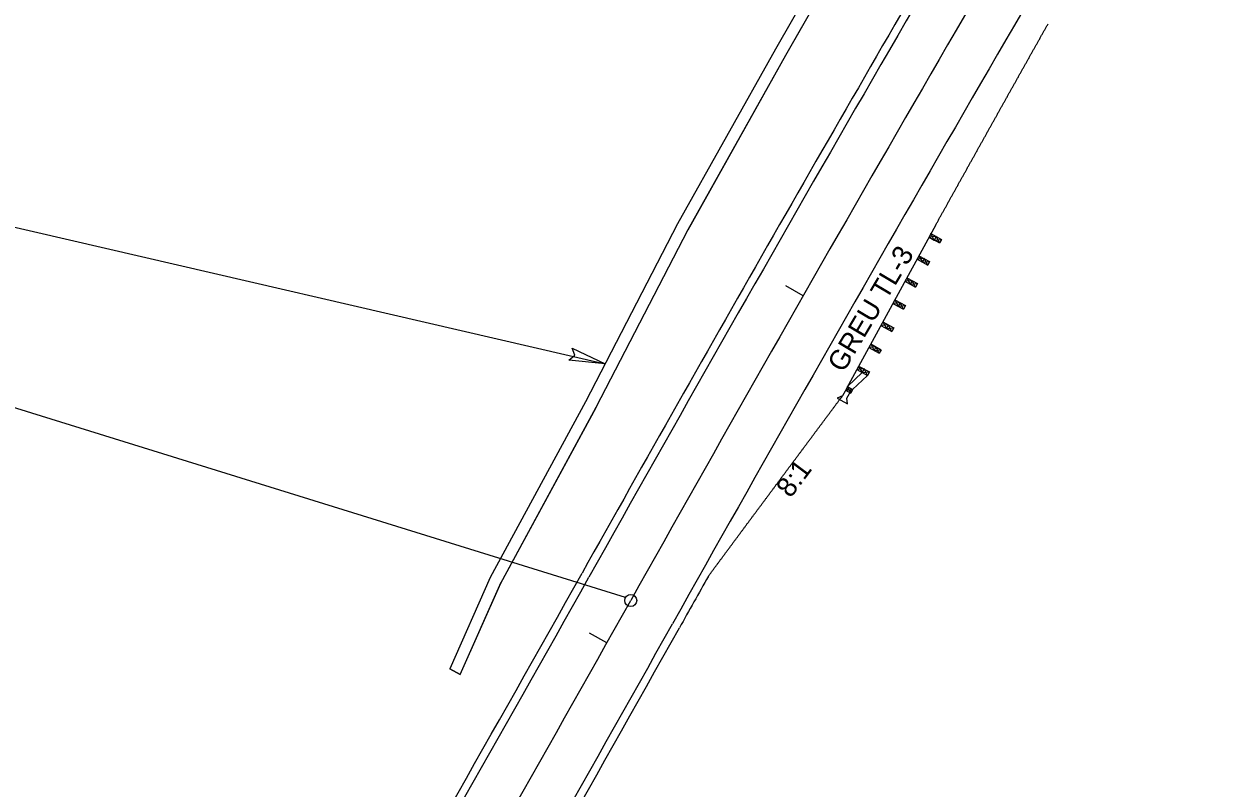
# Model space of a CAD drawing. Extents: x 2138032 to 2141863, y 405316 to 411953.
# Drawn here: x 2140669.7 to 2140967.3, y 409918.8 to 410110.4 of the extents above; entities that cross this region are included whole.
import ezdxf

# ---------------------------------------------------------------- set-up
doc = ezdxf.new("R2010")
doc.units = 0
for name, color, linetype in [('Default', 7, 'Continuous'), ('Prop Dimension Text', 7, 'Continuous'), ('Prop EOT', 7, 'Continuous'), ('Prop Guardrail', 7, 'Continuous'), ('Prop Guardrail Anchor Unit CELL', 7, 'Continuous'), ('Prop Horizontal Alignment', 7, 'Continuous'), ('Prop Horizontal Alignment Station Label', 7, 'Continuous'), ('Prop Horizontal Alignment Tick Small', 7, 'Continuous'), ('Prop Paved Shoulder', 7, 'Continuous'), ('Prop Rip Rap Related Quantities Text', 7, 'Continuous'), ('Prop SS Fill Line', 7, 'Continuous'), ('Prop Terminator CELL', 7, 'Continuous')]:
    doc.layers.add(name, color=color, linetype=linetype)

msp = doc.modelspace()

# ---------------------------------------------------------------- linework, layer by layer
at = {"layer": 'Default'}
msp.add_line((2140598.32, 410075.43), (2140815.52, 410025.19), dxfattribs=at)
msp.add_lwpolyline([(2140779.2, 409947.28), (2140789.36, 409970.23), (2140813.26, 410014.31), (2140836.34, 410058.88), (2140860.81, 410102.57), (2140885.73, 410146.07), (2140908.01, 410191.38), (2140930.41, 410236.37), (2140934.3, 410241.94), (2140931.71, 410243.48), (2140927.72, 410237.7), (2140905.32, 410192.72), (2140883.13, 410147.57), (2140858.2, 410104.03), (2140833.68, 410060.26), (2140810.6, 410015.69), (2140786.72, 409971.66), (2140776.58, 409948.76)], close=True, dxfattribs=at)
at = {"layer": 'Prop EOT'}
for centre, radius, start, end in [((2150502.22, 404534.29), 11112, 149.309258, 150.70339), ((2150502.22, 404534.29), 11088, 149.309258, 150.70339), ((2131141.64, 415397.43), 11088, 329.309258, 330.70339), ((2131141.64, 415397.43), 11112, 329.309258, 330.70339)]:
    msp.add_arc(centre, radius, start, end, dxfattribs=at)
at = {"layer": 'Prop Guardrail'}
msp.add_spline([(2140898.44, 410060.04), (2140898.82, 410060.72), (2140899.2, 410061.4), (2140899.58, 410062.08), (2140899.96, 410062.77), (2140900.34, 410063.45), (2140900.72, 410064.13), (2140901.1, 410064.81), (2140901.48, 410065.49), (2140901.85, 410066.17), (2140902.23, 410066.86), (2140902.61, 410067.54), (2140902.99, 410068.22), (2140903.37, 410068.9), (2140903.75, 410069.58), (2140904.13, 410070.26), (2140904.51, 410070.94), (2140904.89, 410071.63), (2140905.27, 410072.31), (2140905.65, 410072.99), (2140906.03, 410073.67), (2140906.41, 410074.35), (2140906.79, 410075.03), (2140907.17, 410075.71), (2140907.55, 410076.4), (2140907.93, 410077.08), (2140908.31, 410077.76), (2140908.69, 410078.44), (2140909.07, 410079.12), (2140909.45, 410079.8), (2140909.83, 410080.48), (2140910.21, 410081.16), (2140910.59, 410081.84), (2140910.97, 410082.52), (2140911.35, 410083.21), (2140911.73, 410083.89), (2140912.11, 410084.57), (2140912.49, 410085.25), (2140912.87, 410085.93), (2140913.25, 410086.61), (2140913.63, 410087.29), (2140914.01, 410087.97), (2140914.39, 410088.65), (2140914.77, 410089.33), (2140915.15, 410090.01), (2140915.53, 410090.69), (2140915.91, 410091.38), (2140916.3, 410092.06), (2140916.68, 410092.74), (2140917.06, 410093.42), (2140917.44, 410094.1), (2140917.82, 410094.78), (2140918.2, 410095.46), (2140918.58, 410096.14), (2140918.96, 410096.82), (2140919.34, 410097.5), (2140919.73, 410098.18), (2140920.11, 410098.86), (2140920.49, 410099.54), (2140920.87, 410100.22), (2140921.25, 410100.9), (2140921.63, 410101.58), (2140922.01, 410102.26), (2140922.4, 410102.94), (2140922.78, 410103.62), (2140923.16, 410104.3), (2140923.54, 410104.98), (2140923.92, 410105.66), (2140924.31, 410106.34), (2140924.69, 410107.02), (2140925.07, 410107.7), (2140925.45, 410108.38), (2140925.83, 410109.06), (2140926.22, 410109.74), (2140926.6, 410110.42)], degree=3, dxfattribs=at)
at = {"layer": 'Prop Guardrail Anchor Unit CELL'}
for p, q in [((2140898.44, 410060.04), (2140876.02, 410019.02)), ((2140897.23, 410057.81), (2140896.75, 410056.93)), ((2140898.54, 410057.09), (2140896.75, 410056.93)), ((2140896.75, 410056.93), (2140899.38, 410055.49)), ((2140896.75, 410056.93), (2140898.06, 410056.21)), ((2140897.23, 410057.81), (2140899.86, 410056.37)), ((2140898.06, 410056.21), (2140897.23, 410057.81)), ((2140898.54, 410057.09), (2140898.06, 410056.21)), ((2140899.38, 410055.49), (2140898.54, 410057.09)), ((2140898.06, 410056.21), (2140899.86, 410056.37)), ((2140899.86, 410056.37), (2140899.38, 410055.49)), ((2140895.54, 410051.55), (2140893.72, 410051.4)), ((2140893.72, 410051.4), (2140896.4, 410049.94)), ((2140894.2, 410052.28), (2140896.88, 410050.81)), ((2140894.2, 410052.28), (2140895.06, 410050.67)), ((2140895.54, 410051.55), (2140895.06, 410050.67)), ((2140896.4, 410049.94), (2140895.54, 410051.55)), ((2140895.06, 410050.67), (2140896.88, 410050.81)), ((2140896.88, 410050.81), (2140896.4, 410049.94)), ((2140892.52, 410046.02), (2140890.7, 410045.87)), ((2140890.7, 410045.87), (2140893.37, 410044.41)), ((2140891.18, 410046.75), (2140893.85, 410045.29)), ((2140891.18, 410046.75), (2140892.04, 410045.14)), ((2140892.52, 410046.02), (2140892.04, 410045.14)), ((2140892.04, 410045.14), (2140893.85, 410045.29)), ((2140893.37, 410044.41), (2140892.52, 410046.02)), ((2140893.85, 410045.29), (2140893.37, 410044.41)), ((2140888.16, 410041.22), (2140887.68, 410040.34)), ((2140889.49, 410040.49), (2140887.68, 410040.34)), ((2140887.68, 410040.34), (2140890.34, 410038.89)), ((2140888.16, 410041.22), (2140890.82, 410039.76)), ((2140888.16, 410041.22), (2140889.01, 410039.61)), ((2140889.49, 410040.49), (2140889.01, 410039.61)), ((2140889.01, 410039.61), (2140890.82, 410039.76)), ((2140890.34, 410038.89), (2140889.49, 410040.49)), ((2140890.82, 410039.76), (2140890.34, 410038.89)), ((2140886.51, 410034.94), (2140884.66, 410034.81)), ((2140884.66, 410034.81), (2140887.41, 410033.31)), ((2140885.14, 410035.69), (2140887.89, 410034.19)), ((2140885.14, 410035.69), (2140886.03, 410034.06)), ((2140886.51, 410034.94), (2140886.03, 410034.06)), ((2140886.03, 410034.06), (2140887.89, 410034.19)), ((2140887.41, 410033.31), (2140886.51, 410034.94)), ((2140887.89, 410034.19), (2140887.41, 410033.31)), ((2140882.11, 410030.16), (2140884.75, 410028.72)), ((2140882.11, 410030.16), (2140882.95, 410028.56)), ((2140883.43, 410029.44), (2140881.63, 410029.28)), ((2140881.63, 410029.28), (2140884.27, 410027.85)), ((2140883.43, 410029.44), (2140882.95, 410028.56)), ((2140882.95, 410028.56), (2140884.75, 410028.72)), ((2140884.27, 410027.85), (2140883.43, 410029.44)), ((2140884.75, 410028.72), (2140884.27, 410027.85)), ((2140879.09, 410024.63), (2140881.78, 410023.16)), ((2140879.09, 410024.63), (2140879.96, 410023.02)), ((2140879.96, 410023.02), (2140876.26, 410019.46)), ((2140881.3, 410022.29), (2140877.58, 410018.74)), ((2140880.43, 410023.9), (2140878.61, 410023.76)), ((2140878.61, 410023.76), (2140881.3, 410022.29)), ((2140880.43, 410023.9), (2140879.96, 410023.02)), ((2140879.96, 410023.02), (2140881.78, 410023.16)), ((2140881.3, 410022.29), (2140880.43, 410023.9)), ((2140881.78, 410023.16), (2140881.3, 410022.29)), ((2140876.07, 410018.95), (2140875.06, 410017.17)), ((2140875.78, 410018.58), (2140877.58, 410018.74)), ((2140875.78, 410018.58), (2140877.1, 410017.86)), ((2140876.6, 410018.65), (2140876.07, 410018.95)), ((2140876.12, 410016.57), (2140877.13, 410018.35)), ((2140876.26, 410019.46), (2140877.58, 410018.74)), ((2140877.1, 410017.86), (2140876.26, 410019.46)), ((2140877.13, 410018.35), (2140876.6, 410018.65)), ((2140877.58, 410018.74), (2140877.1, 410017.86)), ((2140877.58, 410018.74), (2140877.34, 410018.3)), ((2140875.06, 410017.17), (2140873.73, 410016.58)), ((2140873.73, 410016.58), (2140876.28, 410015.12)), ((2140876.28, 410015.12), (2140876.12, 410016.57))]:
    msp.add_line(p, q, dxfattribs=at)
at = {"layer": 'Prop Horizontal Alignment'}
for centre, start, end in [((2150502.22, 404534.29), 149.309258, 150.70339), ((2131141.64, 415397.43), 329.309258, 330.70339)]:
    msp.add_arc(centre, 11100, start, end, dxfattribs=at)
at = {"layer": 'Prop Horizontal Alignment Station Label'}
msp.add_line((2140820.62, 409966.59), (2140564.81, 410046), dxfattribs=at)
msp.add_circle((2140821.93, 409965.86), 1.5, dxfattribs=at)
at = {"layer": 'Prop Horizontal Alignment Tick Small'}
for p, q in [((2140865.19, 410042.25), (2140860.85, 410044.73)), ((2140815.95, 409955.22), (2140811.59, 409957.67))]:
    msp.add_line(p, q, dxfattribs=at)
at = {"layer": 'Prop Paved Shoulder'}
for centre, radius, start, end in [((2150502.22, 404534.29), 11114, 149.698996, 150.70339), ((2131141.64, 415397.43), 11086, 329.309258, 330.70339), ((2150502.22, 404534.29), 11086, 150.626568, 150.70339), ((2131141.64, 415397.43), 11114, 329.309258, 330.70339)]:
    msp.add_arc(centre, radius, start, end, dxfattribs=at)
msp.add_spline([(2140841.42, 409971.97), (2140841.87, 409972.58), (2140842.33, 409973.19), (2140842.78, 409973.8), (2140843.23, 409974.42), (2140843.69, 409975.03), (2140844.14, 409975.64), (2140844.59, 409976.25), (2140845.05, 409976.86), (2140845.5, 409977.48), (2140845.95, 409978.09), (2140846.41, 409978.7), (2140846.86, 409979.31), (2140847.31, 409979.92), (2140847.77, 409980.54), (2140848.22, 409981.15), (2140848.67, 409981.76), (2140849.13, 409982.37), (2140849.58, 409982.98), (2140850.04, 409983.59), (2140850.49, 409984.21), (2140850.94, 409984.82), (2140851.4, 409985.43), (2140851.85, 409986.04), (2140852.31, 409986.65), (2140852.76, 409987.26), (2140853.21, 409987.87), (2140853.67, 409988.48), (2140854.12, 409989.1), (2140854.58, 409989.71), (2140855.03, 409990.32), (2140855.49, 409990.93), (2140855.94, 409991.54), (2140856.39, 409992.15), (2140856.85, 409992.76), (2140857.3, 409993.37), (2140857.76, 409993.98), (2140858.21, 409994.6), (2140858.67, 409995.21), (2140859.12, 409995.82), (2140859.58, 409996.43), (2140860.03, 409997.04), (2140860.49, 409997.65), (2140860.94, 409998.26), (2140861.39, 409998.87), (2140861.85, 409999.48), (2140862.3, 410000.09), (2140862.76, 410000.7), (2140863.21, 410001.31), (2140863.67, 410001.92), (2140864.12, 410002.53), (2140864.58, 410003.14), (2140865.03, 410003.75), (2140865.49, 410004.37), (2140865.95, 410004.98), (2140866.4, 410005.59), (2140866.86, 410006.2), (2140867.31, 410006.81), (2140867.77, 410007.42), (2140868.22, 410008.03), (2140868.68, 410008.64), (2140869.13, 410009.25), (2140869.59, 410009.86), (2140870.04, 410010.47), (2140870.5, 410011.08), (2140870.95, 410011.69), (2140871.41, 410012.3), (2140871.87, 410012.91), (2140872.32, 410013.52), (2140872.78, 410014.13), (2140873.23, 410014.74), (2140873.69, 410015.35), (2140874.15, 410015.95), (2140875.06, 410017.17)], degree=3, dxfattribs=at)
at = {"layer": 'Prop Rip Rap Related Quantities Text'}
msp.add_line((2140779.2, 409947.28), (2140776.58, 409948.76), dxfattribs=at)
at = {"layer": 'Prop SS Fill Line'}
for p, q in [((2140860.8, 410102.54), (2140885.73, 410146.07)), ((2140836.3, 410058.8), (2140860.81, 410102.57)), ((2140813.26, 410014.31), (2140836.34, 410058.88)), ((2140789.36, 409970.23), (2140813.23, 410014.26)), ((2140779.2, 409947.28), (2140789.46, 409970.44))]:
    msp.add_line(p, q, dxfattribs=at)
at = {"layer": 'Prop Terminator CELL'}
msp.add_lwpolyline([(2140807.27, 410029.11), (2140815.52, 410025.19), (2140806.37, 410026.09), (2140807.91, 410027.32)], close=True, dxfattribs=at)

# ---------------------------------------------------------------- texts
at = {"layer": 'Prop Dimension Text'}
msp.add_text('8:1', height=5, rotation=53.3495, dxfattribs=at).set_placement((2140862.02, 409991.34))
at = {"layer": 'Prop Guardrail Anchor Unit CELL'}
msp.add_text('GREU TL-3', height=5, rotation=59.3093, dxfattribs=at).set_placement((2140875.28, 410022.75))

doc.saveas('drawing.dxf')
